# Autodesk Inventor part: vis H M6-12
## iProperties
Author: chr
Shininess: 20.0
PropertySet Name: _Private Model Information
Length Units: 11269
Angle Units: 11286
Time Units: 11279
Mass Units: 11290
Length Display Precision: 3
Angle Display Precision: 2
Compacted: False
Created: 2001-06
Part Number: vis H M6-12
Material: Par défaut
Document SubType Name: Modélisation
Designer: chr
Control State: 0
Master: False
Checked Out: False
PropertySet Name: Design Tracking Control
Density: 0.0
Volumn: 0.0
Area: 0.0
PropertySet Name: Model Information
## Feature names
1. Base1
